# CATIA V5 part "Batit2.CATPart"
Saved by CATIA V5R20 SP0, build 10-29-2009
Part number: Batit2
Bounding box of the stored display mesh (mm): x -27.621 to 19.889, y -39.979 to 61.759, z -116.662 to 22.951
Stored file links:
  C:\Users\ASUS\Desktop\Think Motion IAO\Batit2.CATPart
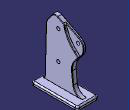
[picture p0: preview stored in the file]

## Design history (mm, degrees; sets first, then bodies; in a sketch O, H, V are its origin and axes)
Body1 (main body)
  Plane1: stored without definition
  Sketch1 on Plane1, origin (0, 0, 0), H (0, 1, 0), V (0, 0, 1)
    line L1 (-29.9491, -109.6622) -> (34.6855, -109.6622)
    line L2 (34.6855, -109.6622) -> (29.0488, -54.4206)
    line L3 (29.0488, -54.4206) -> (60.9903, -11.2045)
    line L4 (60.9903, -11.2045) -> (-9.3026, 25.8087)
    line L5 (-9.3026, 25.8087) -> (-27.3039, 1.4534)
    line L6 (-27.3039, 1.4534) -> (-29.9491, -109.6622)
    horizontal: L1 H
    parallelism: L5 L3
  Pad1: profile Sketch1, direction (1, 0, 0), length -10
  DatumPoint1
  Sketch2 on start face of Pad1, origin (0, 0, 0), H (0, 1, 0), V (0, 0, 1)
    point P1 (-2.0969, -8.6894)
    point P2 (-2.0969, -8.6894)
    line L1 (61.9375, -11.5626) -> (44.2687, -34.9984)
    line L2 (44.2687, -34.9984) -> (35.277, -26.5445)
    line L3 (12.8762, 13.9308) -> (9.7867, 29.5945)
    line L4 (9.7867, 29.5945) -> (61.9375, -11.5626)
    arc A1 centre (87.0936, 28.5694) radius 75.6472 from (35.277, -26.5445) to (12.8762, 13.9308) cw
    radius A1 = 75.6472
    coincidence: P1 P2
    tangency: A1 L2, A1 L3
  Pocket1: profile Sketch2, direction (-1, 0, 0), length 5
  Point1 "Point.C": stored without definition
  Point2 "Point.G": stored without definition
  Sketch3 on end face of Pocket1, origin (-5, 38.4908, -10.8837), H (0, 1, 0), V (0, 0, 1)
    point P1 (0, 0)
    reference projected point E1 (0, 0) from Point1
    coincidence: E1 P1
  Hole1: placed by Sketch3, at (-5, 38.4908, -10.8837) direction (-1, 0, 0), diameter 7, depth 10
  Sketch4 on start face of Pad1, origin (0, 0.0005, -63), H (0, 1, 0), V (0, 0, 1)
    point P1 (0, 0)
    reference projected point E1 (0, 0) from Point2
    coincidence: E1 P1
  Hole2: placed by Sketch4, at (0, 0.0005, -63) direction (-1, 0, 0), diameter 7, depth 10
  Fillet1: radius 10, on edge [face of Pad1 from Sketch1.L4 | face of Pad1 from Sketch1.L5]
  Fillet2: radius 20, on edge [face of Pad1 from Sketch1.L5 | face of Pad1 from Sketch1.L6]
  Fillet3: radius 20, on edge [face of Pad1 from Sketch1.L3 | face of Pad1 from Sketch1.L4]
  Fillet4: radius 30, on edge [face of Pad1 from Sketch1.L2 | face of Pad1 from Sketch1.L3]
  Fillet5: radius 5, on edge [face of Pad1 from Sketch1.L3 | face of Pocket1], deactivated
  Fillet6: radius 5, on edge [face of Pocket1 from Sketch2.L3 | face of Pad1 from Sketch1.L4]
  Sketch5 on face of Pad1 from Sketch1.L1, origin (0, 0, -109.6622), H (1, 0, 0), V (0, -1, 0)
    line L1 (19.8889, 39.9787) -> (-27.6207, 39.9787)
    line L2 (-27.6207, 39.9787) -> (-27.6207, -61.7594)
    line L3 (-27.6207, -61.7594) -> (19.8889, -61.7594)
    line L4 (19.8889, -61.7594) -> (19.8889, 39.9787)
    horizontal: L1 H, L3 H
    vertical: L2 V, L4 V
  Pad2: profile Sketch5, direction (0, 0, -1), length 7
  Fillet7: radius 20, on edge [start face of Pad2 | face of Pad1 from Sketch1.L2]
  Fillet8: radius 5, on edge [face of Pad1 from Sketch1.L6 | start face of Pad2]
  Fillet9: radius 5, on edge [face of Pad2 from Sketch5.L4 | face of Pad2 from Sketch5.L3]
  Fillet10: radius 5, on edge [face of Pad2 from Sketch5.L1 | face of Pad2 from Sketch5.L4]
  Fillet11: radius 5, on edge [face of Pad2 from Sketch5.L2 | face of Pad2 from Sketch5.L1]
  Fillet12: radius 5, on edge [face of Pad2 from Sketch5.L3 | face of Pad2 from Sketch5.L2]
  Fillet13: radius 3, on edge [start face of Pad2 | face of Pad2 from Sketch5.L1]
  Fillet14: radius 1, on edge [face of Pad1 from Sketch1.L6 | start face of Pad1]
  Fillet15: radius 1, on edge [end face of Pad1 | face of Pad1 from Sketch1.L6]
  Fillet16: radius 1, on edge [face of Fillet7 | start face of Pad1], deactivated
  Fillet17: radius 1, on edge [end face of Pocket1 | face of Fillet3]
  Fillet18: radius 1, on edge [face of Pocket1 | end face of Pocket1], deactivated
  Fillet19: radius 1, on edge [end face of Pocket1 | face of Fillet5], deactivated
  Point3 "Point.O": stored without definition
  Point4 "Point.A": stored without definition
  Fillet20: radius 1, on edge [face of Pad1 from Sketch1.L3 | face of Pocket1 from Sketch2.L2]
  Sketch6 on start face of Pad1, origin (0, 0, 0), H (0, 1, 0), V (0, 0, 1)
    point P1 (0, 0)
    reference projected point E1 (0, 0) from Point4
    coincidence: E1 P1
  Hole3: placed by Sketch6, at (0, 0, 0) direction (-1, 0, 0), diameter 7, depth 10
